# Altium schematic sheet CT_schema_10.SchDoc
size 278 x 170 mm
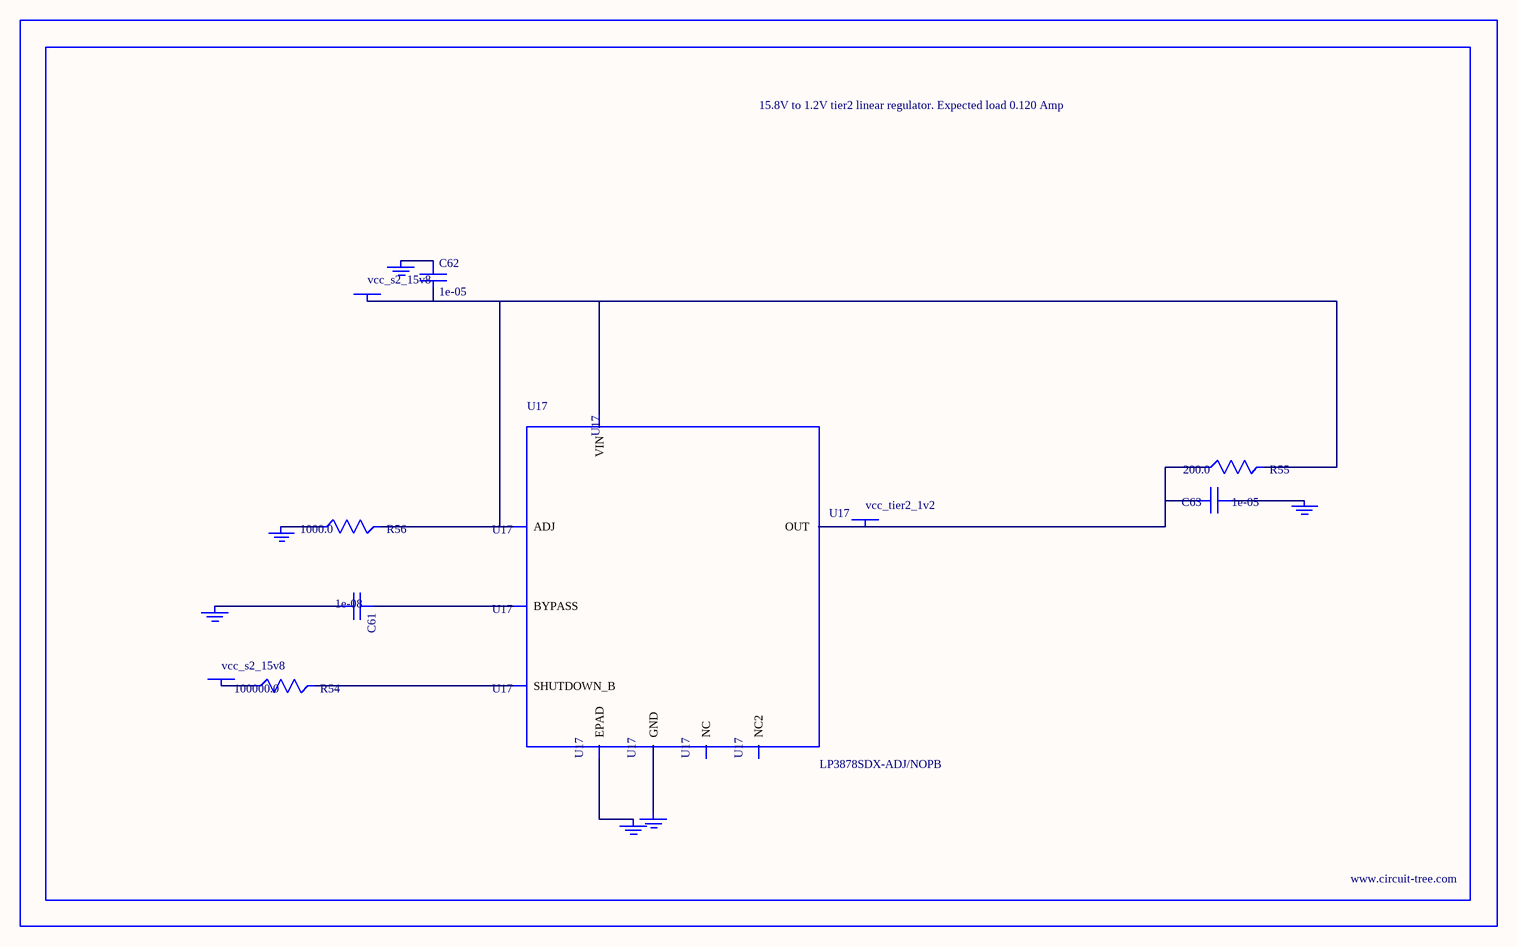
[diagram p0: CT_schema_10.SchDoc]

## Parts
BORDER9  (no value)
C61  1e-08  [C0402]
C62  1e-05  [C1210]
C63  1e-05  [C0805]
GND_INSTANCE_9_0  (no value)
GND_INSTANCE_9_1  (no value)
GND_INSTANCE_9_2  (no value)
GND_INSTANCE_9_3  (no value)
GND_INSTANCE_9_4  (no value)
GND_INSTANCE_9_5  (no value)
POWER_INSTANCE_9_0  vcc_s2_15v8
POWER_INSTANCE_9_1  vcc_s2_15v8
POWER_INSTANCE_9_2  vcc_tier2_1v2
R54  100000.0  [R0603]
R55  200.0  [R0603]
R56  1000.0  [R0603]
U17  LP3878SDX-ADJ/NOPB  [WSON-8]

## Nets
NetC61_1: C61.1 U17.1(BYPASS)
NetC61_2: C61.2 GND_INSTANCE_9_0.0(GND)
NetC62_1: C62.1 GND_INSTANCE_9_1.0(GND)
NetC62_2: C62.2 POWER_INSTANCE_9_0.0(PWR) R55.2 R56.2 U17.4(VIN) U17.6(ADJ)
NetC63_1: C63.1 GND_INSTANCE_9_2.0(GND)
NetC63_2: C63.2 POWER_INSTANCE_9_2.0(PWR) R55.1 U17.5(OUT)
NetGND_INSTANCE_9_3_0: GND_INSTANCE_9_3.0(GND) R56.1
NetGND_INSTANCE_9_4_0: GND_INSTANCE_9_4.0(GND) U17.PAD(EPAD)
NetGND_INSTANCE_9_5_0: GND_INSTANCE_9_5.0(GND) U17.3(GND)
NetPOWER_INSTANCE_9_1_0: POWER_INSTANCE_9_1.0(PWR) R54.1
NetR54_2: R54.2 U17.8(SHUTDOWN_B)

Not connected (* = marked no-connect by the designer): U17 2(NC) 7(NC2)

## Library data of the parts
BORDER9 = BORDER_PAGE9
C61 = C0402C103K3RAC
C62 = C1210C106K5PACTU
C63 = GRM219R60J106ME19D
GND_INSTANCE_9_0-GND_INSTANCE_9_5 = GND
POWER_INSTANCE_9_0-POWER_INSTANCE_9_2 = PWR
R54 = RC0603JR-07100KL
R55 = RC0603JR-07200RL
R56 = RC0603JR-071KL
